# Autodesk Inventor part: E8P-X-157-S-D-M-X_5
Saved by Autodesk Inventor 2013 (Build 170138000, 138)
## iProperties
Created: 2012-07
Part Number: E8P-X-157-S-D-M-X_5
Material: Allgemein
Document SubType Name: Modeling
Designer: rYan
Density: 1 g/cm^3
Mass: 0.0490807 g
Surface Area: 5.89347 cm^2
Volume: 0.0490807 cm^3
Author: rYan
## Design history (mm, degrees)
node "E8P-X-157-S-D-M-X_51"
node "E8P-X-157-S-D-M-X_5"
node "Basis1"
